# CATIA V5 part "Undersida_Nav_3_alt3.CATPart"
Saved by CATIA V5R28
Part number: Undersida_Nav_3
Bounding box of the stored display mesh (mm): x -107.108 to 82.814, y -82.361 to 109.652, z 0 to 70
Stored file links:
  H:\Maskiningenjör\Examensarbete\Klart\Klart & Skickas\Undersida_Nav_3_alt3.CATPart
  H:\Examensarbete\FullAssembly_KlartMedStativ\Assembly_Fullt+Stativ.CATProduct
  H:\Maskiningenjör\Examensarbete\Klart\Klart & Skickas\HJALPMEDEL.CATPart
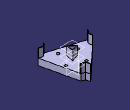
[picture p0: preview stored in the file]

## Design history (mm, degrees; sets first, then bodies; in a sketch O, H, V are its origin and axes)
Set1
  DatumPoint1 to DatumPoint4: linked copy from another document
Set2 "Sketches"
  Sketch1 "BasHubSketch" on xy-plane, origin (0, 0, 0), H (1, 0, 0), V (0, 1, 0)
    point P1 (14.1037, 15.4471)
    construction line L1 (14.1037, 15.4471) -> (-19.7235, 4.083)
    point P2 (-19.7235, 4.083)
    construction line L2 (-19.7235, 4.083) -> (7.0316, -19.5301)
    point P3 (7.0316, -19.5301)
    construction line L3 (7.0316, -19.5301) -> (14.1037, 15.4471)
    construction circle A1 centre (0.4706, 0) radius 10.3014
    point P4 (0.4706, 0)
    point P5 (2.4567, 169.7723)
    line L4 (2.4567, 169.7723) -> (-91.9658, -20.1866)
    point P6 (-91.9658, -20.1866)
    line L5 (-91.9658, -20.1866) -> (-147.5495, -83.1664)
    line L6 (-147.5495, -83.1664) -> (64.171, -69.9592)
    point P8 (64.171, -69.9592)
    line L7 (64.171, -69.9592) -> (146.5049, -86.6062)
    line L8 (146.5049, -86.6062) -> (29.2069, 90.1455)
    point P10 (29.2069, 90.1455)
    line L9 (29.2069, 90.1455) -> (2.4567, 169.7723)
    construction line L10 (29.2069, 90.1455) -> (64.171, -69.9592)
    construction line L11 (64.171, -69.9592) -> (-91.9658, -20.1866)
    construction line L12 (-91.9658, -20.1866) -> (29.2069, 90.1455)
    reference intersected line E1 through (0, 0) direction (0, 1) from yz-plane
    length L3 = 35.685
    length L1 = 35.685
    length L2 = 35.685
    length L9 = 84
    length L7 = 84
    length L5 = 84
    angle L9 L8 = 165
    angle L4 L5 = 165
    angle L6 L7 = 165
    distance P6 P8 = 163.878
    distance P6 P10 = 163.878
    distance P8 P10 = 163.878
    length L8 = 212.132 (reference)
    length L4 = 212.132 (reference)
    angle L10 V = 12.319
    length L6 = 212.132 (reference)
    distance P1 P10 = 76.21
    distance P2 P6 = 76.21
    angle L2 L5 = 90 (reference)
    distance P8 P3 = 76.2102
    distance P5 E1 = 2.4567
    tangency: A1 L3, A1 L1, A1 L2
    coincidence: P4 H
  Sketch2 "BasTriangelKoppling" on xy-plane, origin (0, 0, 0), H (1, 0, 0), V (0, 1, 0)
    line L1 (29.2069, 90.1455) -> (-91.9658, -20.1866)
    point P1 (29.2069, 90.1455)
    point P2 (-91.9658, -20.1866)
    line L2 (-91.9658, -20.1866) -> (64.171, -69.9592)
    point P3 (64.171, -69.9592)
    line L3 (64.171, -69.9592) -> (29.2069, 90.1455)
    reference projected point E1 (29.2069, 90.1455) from vertex [element of Sketch1 | element of Sketch1]
    reference projected point E2 (-91.9658, -20.1866) from vertex [element of Sketch1 | element of Sketch1]
    reference projected point E3 (64.171, -69.9592) from vertex [element of Sketch1 | element of Sketch1]
    coincidence: P1 E1, P2 E2, P3 E3
  Sketch3 "BenSketch" on Plane1, origin (0, 0, 30), H (1, 0, 0), V (0, 1, 0)
    point P1 (28.7362, 90.1456)
    line L1 (28.7362, 90.1456) -> (46.3521, 83.0267)
    point P2 (46.3521, 83.0267)
    line L2 (22.6855, 108.1564) -> (28.7362, 90.1456)
    point P3 (-92.4365, -20.1865)
    line L3 (-92.4365, -20.1865) -> (-95.0793, -1.3712)
    point P4 (-95.0793, -1.3712)
    line L4 (-105.009, -34.432) -> (-92.4365, -20.1865)
    point P5 (63.7003, -69.9591)
    line L5 (82.3234, -73.7245) -> (63.7003, -69.9591)
    line L6 (-107.1076, -33.7873) -> (-94.5183, -19.5229)
    point P7 (-94.5183, -19.5229)
    line L7 (-94.5183, -19.5229) -> (-96.8381, -3.007)
    line L8 (64.1665, -72.0938) -> (51.0232, -82.3608)
    point P9 (64.1665, -72.0938)
    line L9 (64.1665, -72.0938) -> (82.8145, -75.8642)
    line L10 (30.3518, 91.6167) -> (45.8149, 85.3678)
    point P12 (30.3518, 91.6167)
    line L11 (30.3518, 91.6167) -> (24.2931, 109.6515)
    line L12 (82.8145, -75.8642) -> (82.3234, -73.7245)
    point P15 (82.3234, -73.7245)
    line L13 (51.0232, -82.3608) -> (48.7272, -81.6555)
    point P16 (48.7272, -81.6555)
    line L14 (-107.1076, -33.7873) -> (-105.009, -34.432)
    point P18 (-95.0793, -1.3712)
    line L15 (-95.0793, -1.3712) -> (-96.8381, -3.007)
    line L16 (24.2931, 109.6515) -> (22.6855, 108.1564)
    line L17 (45.8149, 85.3678) -> (46.3521, 83.0267)
    point P20 (46.3521, 83.0267)
    line L18 (63.7003, -69.9591) -> (48.7272, -81.6555)
    construction line L19 (28.7362, 90.1456) -> (-92.4365, -20.1865)
    construction line L20 (-92.4365, -20.1865) -> (63.7003, -69.9591)
    construction line L21 (63.7003, -69.9591) -> (28.7362, 90.1456)
    construction line L22 (63.7003, -69.9591) -> (146.0342, -86.6061)
    construction line L23 (146.0342, -86.6061) -> (28.7362, 90.1456)
    construction line L24 (28.7362, 90.1456) -> (1.986, 169.7724)
    construction line L25 (1.986, 169.7724) -> (-92.4365, -20.1865)
    construction line L26 (-92.4365, -20.1865) -> (-148.0202, -83.1663)
    construction line L27 (-148.0202, -83.1663) -> (63.7003, -69.9591)
    construction line L28 (28.7362, 90.1456) -> (49.7278, 109.2592)
    construction line L29 (24.2931, 109.6515) -> (-96.8381, -3.007)
    construction line L30 (46.3521, 83.0267) -> (82.3234, -73.7245)
    construction line L31 (51.0232, -82.3608) -> (-105.009, -34.432)
    point P25 (46.2038, 10.1594)
    construction circle A1 centre (0, 0) radius 47.3075
    point P26 (0, 0)
    reference intersected line E1 through (0, 0) direction (0, 1) from yz-plane
    point P27 (-20.1941, 4.0829)
    point P28 (13.633, 15.4472)
    construction line L32 (13.633, 15.4472) -> (-20.1941, 4.0829)
    point P29 (6.5612, -19.5301)
    construction line L33 (6.5612, -19.5301) -> (13.633, 15.4472)
    construction line L34 (-20.1941, 4.0829) -> (6.5612, -19.5301)
    angle L2 L1 = 130.574
    angle L3 L4 = 130.574
    distance L6 L4 = 2
    distance L9 L5 = 2
    distance L2 L11 = 2
    angle L18 L5 = 130.574
    distance P15 P5 = 19
    distance P16 P5 = 19
    length L2 = 19
    length L1 = 19
    length L4 = 19
    length L3 = 19
    length L23 = 212.132
    length L22 = 84
    length L27 = 212.132
    length L26 = 84
    length L25 = 212.132
    length L24 = 84
    length L20 = 163.878
    length L19 = 163.878
    length L21 = 163.878
    angle E1 L21 = 12.319
    angle L24 L23 = 165 (reference)
    distance P1 P28 = 76.21
    distance P29 P5 = 76.21
    distance P27 P3 = 76.21
    angle L32 L3 = 79.4257
    angle L18 L34 = 79.4257
    angle L1 L33 = 79.4257
    parallelism: L7 L3, L10 L1, L18 L8, L9 L5
    coincidence: P4 P18, P20 L1, P2 P20, L5 L22, L2 L24, L28 L19, P12 L28, P9 L21, P7 L20, L15 L29, L16 L29, L17 L30, L12 L30, L13 L31, L14 L31, L4 L26, P25 L21, P26 O
    tangency: A1 L20, A1 L21, A1 L19
  Sketch4 "BaseSketch" on xy-plane, origin (0, 0, 0), H (1, 0, 0), V (0, 1, 0)
    line L1 (45.8149, 85.3678) -> (82.8145, -75.8642)
    point P1 (45.8149, 85.3678)
    point P2 (82.8145, -75.8642)
    line L2 (24.2931, 109.6515) -> (-96.8381, -3.007)
    point P3 (24.2931, 109.6515)
    point P4 (-96.8381, -3.007)
    line L3 (-107.1076, -33.7873) -> (51.0232, -82.3608)
    point P5 (-107.1076, -33.7873)
    point P6 (51.0232, -82.3608)
    line L4 (51.0232, -82.3608) -> (64.1665, -72.0938)
    point P7 (64.1665, -72.0938)
    line L5 (64.1665, -72.0938) -> (82.8145, -75.8642)
    line L6 (-107.1076, -33.7873) -> (-94.5183, -19.5229)
    point P8 (-94.5183, -19.5229)
    line L7 (-94.5183, -19.5229) -> (-96.8381, -3.007)
    line L8 (24.2931, 109.6515) -> (30.3518, 91.6167)
    point P9 (30.3518, 91.6167)
    line L9 (30.3518, 91.6167) -> (45.8149, 85.3678)
    reference projected point E1 (45.8149, 85.3678) from vertex [element of Sketch3 | element of Sketch3]
    reference projected point E2 (24.2931, 109.6515) from vertex [element of Sketch3 | element of Sketch3]
    reference projected point E3 (30.3518, 91.6167) from vertex [element of Sketch3 | element of Sketch3]
    reference projected point E4 (82.8145, -75.8642) from vertex [element of Sketch3 | element of Sketch3]
    reference projected point E5 (51.0232, -82.3608) from vertex [element of Sketch3 | element of Sketch3]
    reference projected point E6 (64.1665, -72.0938) from vertex [element of Sketch3 | element of Sketch3]
    reference projected point E7 (-96.8381, -3.007) from vertex [element of Sketch3 | element of Sketch3]
    reference projected point E8 (-107.1076, -33.7873) from vertex [element of Sketch3 | element of Sketch3]
    reference projected point E9 (-94.5183, -19.5229) from vertex [element of Sketch3 | element of Sketch3]
    coincidence: P1 E1, P3 E2, P9 E3, P2 E4, P6 E5, P7 E6, P4 E7, P5 E8, P8 E9
  Sketch5 "UndersideHole" on xy-plane, origin (0, 0, 0), H (1, 0, 0), V (0, 1, 0)
    circle A1 centre (0, 0) radius 26
    radius A1 = 26
    concentricity: A1 O
  Sketch6 "MiddleTriangle" on Plane1, origin (0, 0, 30), H (1, 0, 0), V (0, 1, 0)
    point P1 (-20.1941, 4.0829)
    point P2 (13.633, 15.4472)
    line L1 (13.633, 15.4472) -> (-20.1941, 4.0829)
    point P3 (6.5612, -19.5301)
    line L2 (6.5612, -19.5301) -> (13.633, 15.4472)
    construction circle A1 centre (0, 0) radius 10.3014
    line L3 (-20.1941, 4.0829) -> (6.5612, -19.5301)
    reference projected line E1 (29.15, 89.9784) -> (46.7659, 82.8595) from Sketch3.L1
    reference projected line E2 (64.0282, -69.7029) -> (49.0551, -81.3993) from Sketch3.L18
    reference projected point E3 (-92.4365, -20.1865) from vertex [element of Sketch3 | element of Sketch3]
    reference projected point E4 (-92.4365, -20.1865) from vertex [element of Sketch3 | element of Sketch3]
    reference projected point E5 (28.7362, 90.1456) from vertex [element of Sketch3 | element of Sketch3]
    reference projected point E6 (63.7003, -69.9591) from vertex [element of Sketch3 | element of Sketch3]
    reference projected line E7 (-92.4323, -20.2164) -> (-95.0751, -1.4011) from Sketch3.L3
    length L2 = 35.685
    length L1 = 35.685
    length L3 = 35.685
    angle E1 L2 = 79.4257 (reference)
    angle L3 E2 = 79.4257 (reference)
    distance P1 E3 = 76.21 (reference)
    distance E4 P1 = 76.21
    distance P2 E5 = 76.21
    distance P3 E6 = 76.21
    angle E7 L1 = 79.4257 (reference)
    tangency: A1 L2, A1 L3, A1 L1
  Sketch7 "InnerTriangle" on Plane3, origin (0, 0, 70), H (1, 0, 0), V (0, 1, 0)
    construction line L1 (13.6331, 15.4471) -> (-20.1941, 4.083)
    point P3 (6.5611, -19.5301)
    construction line L2 (6.5611, -19.5301) -> (13.6331, 15.4471)
    construction line L3 (-20.1941, 4.083) -> (6.5611, -19.5301)
    point P4 (0, 0)
    construction circle A1 centre (0, 0) radius 10.3014
    line L4 (9.2639, 10.4966) -> (-13.7223, 2.7745)
    line L5 (-13.7223, 2.7745) -> (4.4584, -13.2711)
    line L6 (4.4584, -13.2711) -> (9.2639, 10.4966)
    construction circle A2 centre (0, 0) radius 7
    reference projected line E1 (-19.9341, 3.8534) -> (6.8212, -19.7596) from Sketch6.L3
    reference projected line E2 (64.0282, -69.7029) -> (49.0551, -81.3993) from Sketch3.L18
    reference projected line E3 (6.5883, -19.3957) -> (13.6601, 15.5816) from Sketch6.L2
    reference projected line E4 (29.15, 89.9784) -> (46.7659, 82.8595) from Sketch3.L1
    reference projected line E5 (-92.4323, -20.2164) -> (-95.0751, -1.4011) from Sketch3.L3
    reference projected point E6 (63.7003, -69.9591) from vertex [element of Sketch3 | element of Sketch3]
    length L1 = 35.685
    length L2 = 35.685
    length L3 = 35.685
    angle E1 E2 = 79.4257 (reference)
    angle E3 E4 = 79.4257 (reference)
    angle E5 L1 = 79.426
    distance P3 E6 = 76.2101 (reference)
    radius A2 = 7
    tangency: A1 L1, A1 L2, A1 L3, A2 L5, A2 L4, A2 L6
    coincidence: P4 O
    parallelism: L5 L3, L4 L1, L6 L2
Set3 "ExtraSketches"
  Sketch8 on Plane2, origin (0, 0, 70), H (1, 0, 0), V (0, 1, 0)
    point P1 (29.2069, 90.1455)
    construction line L1 (29.2069, 90.1455) -> (45.8796, 83.3617)
    construction line L2 (45.8796, 83.3617) -> (43.2556, 102.9374)
    point P3 (43.2556, 102.9374)
    construction line L3 (43.2556, 102.9374) -> (22.8378, 109.1043)
    construction line L4 (22.8378, 109.1043) -> (29.2069, 90.1455)
    point P5 (-91.9658, -20.1866)
    construction line L5 (-91.9658, -20.1866) -> (-94.491, -2.3646)
    construction line L6 (-94.491, -2.3646) -> (-110.0683, -14.416)
    point P7 (-110.0683, -14.416)
    construction line L7 (-110.0683, -14.416) -> (-105.2, -35.1818)
    construction line L8 (-105.2, -35.1818) -> (-91.9658, -20.1866)
    point P9 (64.171, -69.9592)
    construction line L9 (64.171, -69.9592) -> (49.9993, -81.057)
    construction line L10 (49.9993, -81.057) -> (68.2247, -88.5217)
    point P11 (68.2247, -88.5217)
    construction line L11 (68.2247, -88.5217) -> (83.7743, -73.9227)
    construction line L12 (83.7743, -73.9227) -> (64.171, -69.9592)
    reference projected point E1 (29.2069, 90.1455) from vertex [element of Sketch2 | element of Sketch2]
    construction line L13 (4.7862, 67.9096) -> (62.2514, 120.2338)
    reference projected line E2 (27.0028, 88.1386) -> (-89.0375, -17.5203) from Sketch2.L1
    construction line L14 (-154.2129, -0.3438) -> (-41.3139, -36.3332)
    reference projected line E3 (-89.7482, -20.8935) -> (59.6074, -68.5044) from Sketch2.L2
    reference projected point E4 (-91.9658, -20.1866) from vertex [element of Sketch2 | element of Sketch2]
    construction line L15 (59.6572, -49.2902) -> (72.3238, -107.2918)
    reference projected line E5 (63.5408, -67.0736) -> (30.083, 86.1336) from Sketch2.L3
    reference projected point E6 (64.171, -69.9592) from vertex [element of Sketch2 | element of Sketch2]
    reference projected line E7 (-92.1398, -20.3838) -> (-149.5902, -85.4786) from Sketch1.L5
    reference projected line E8 (29.1039, 90.4521) -> (1.4553, 172.753) from Sketch1.L9
    reference projected line E9 (63.7621, -69.8765) -> (148.8611, -87.0826) from Sketch1.L7
    point P19 (64.811, -72.8901)
    line L16 (64.811, -72.8901) -> (78.2238, -75.602)
    line L17 (78.2238, -75.602) -> (67.5846, -85.5908)
    point P21 (67.5846, -85.5908)
    line L18 (67.5846, -85.5908) -> (55.1146, -80.4834)
    line L19 (55.1146, -80.4834) -> (64.811, -72.8901)
    line L20 (-96.5519, -7.0815) -> (-107.21, -15.3271)
    point P24 (-107.21, -15.3271)
    line L21 (-107.21, -15.3271) -> (-103.8791, -29.5353)
    line L22 (-103.8791, -29.5353) -> (-94.8241, -19.2754)
    point P26 (-94.8241, -19.2754)
    line L23 (-94.8241, -19.2754) -> (-96.5519, -7.0815)
    point P27 (41.0374, 100.9177)
    line L24 (41.0374, 100.9177) -> (42.8328, 87.5237)
    line L25 (42.8328, 87.5237) -> (31.4251, 92.1653)
    point P29 (31.4251, 92.1653)
    line L26 (31.4251, 92.1653) -> (27.0673, 105.1371)
    line L27 (27.0673, 105.1371) -> (41.0374, 100.9177)
    length L1 = 18
    length L4 = 20
    angle L4 L1 = 130.71
    length L8 = 20
    length L5 = 18
    angle L5 L8 = 130.505
    length L12 = 20
    length L9 = 18
    angle L9 L12 = 130.505
    distance P7 P5 = 19
    distance P1 P3 = 19
    distance P11 P9 = 19
    distance P19 P21 = 13
    distance P19 P9 = 3
    distance P24 P26 = 13
    distance P26 P5 = 3
    distance P29 P1 = 3
    distance P29 P27 = 13
    coincidence: P1 E1, L13 E2, P3 L13, L14 E3, P7 L14, P5 E4, L15 E5, P9 E6, P11 L15, L8 E7, L4 E8, L12 E9, P19 L15, P21 L15, P24 L14, P26 L14, P27 L13, P29 L13
    parallelism: L18 L10, L19 L9, L17 L11, L16 L12, L21 L7, L22 L8, L20 L6, L23 L5, L24 L2, L25 L1, L26 L4, L27 L3
Set4 "Fills"
  Fill1 "UnderFill_Bas": Boundary Sketch4, InnerBoundaries {fillinnerboundary Boundaries Sketch5}
  Fill2 "UpperFill_Bas": Boundary (edge of Extrude2; edge of Extrude2; edge of Extrude2; edge of Extrude2; edge of Extrude2; edge of Extrude2; edge of Extrude2; edge of Extrude2; edge of Extrude2)
  Fill3 "CornerTopFill1": Boundary Sketch3
  Fill4: Boundary (edge of Extrude1; edge of Extrude1; edge of Extrude1; edge of Extrude1; edge of Extrude1; edge of Extrude1)
  Fill5: Boundary (edge of Extrude1; edge of Extrude1; edge of Extrude1; edge of Extrude1; edge of Extrude1; edge of Extrude1)
  Fill6: Boundary (edge of Extrude1; edge of Extrude1; edge of Extrude1; edge of Extrude1; edge of Extrude1; edge of Extrude1)
  Fill7 "TriangleFill": Boundary (edge of Extrude4; edge of Extrude4; edge [face of CloseSurface1 | face of CloseSurface1])
Set5 "Planes"
  Plane1: type Offset, RefPlane xy-plane, Offset 30
  Plane2 "CornerPillarsPlane": type Offset, RefPlane Plane1, Offset 40
  Plane3 "TriangleLengthPlane": type Offset, RefPlane Plane1, Offset 40
Set6 "Extrudes"
  Extrude1 "CornerPillar_Extrudes": Element1 Sketch3, Lim1 20, Lim2 0, FirstUpto Plane2
  Extrude2 "Bas_Extrude": Element1 Sketch4, Lim1 20, Lim2 0, FirstUpto Plane1
  Extrude3 "MiddleBaseHole": Element1 Sketch5, Lim1 18, Lim2 0
  Extrude4 "TriangleExtrude": Element1 Sketch6, Lim1 29, Lim2 0, FirstUpto Plane3
Set7 "Joins"
  Join1: Elements (Fill1; Extrude2; Extrude3; Trim1; Fill4; Fill5; Fill6)
Set8 "Trims"
  Trim1: Trimmed (Extrude1; Fill2; Extrude4)
Body1 (main body)
  CloseSurface1: CloseElement Join1
  Pocket1: profile Sketch7, direction (0, 0, -1), length 30
  Sketch9, origin (19.0383, -48.2652, 0), H (1, 0, 0), V (0, -1, 0), geometry linked from another document
  Hole1: placed by Sketch9, at (18.7916, -47.5306, 0) direction (0, 0, 1), diameter 12, through (limit type 3)
  Sketch10, origin (47.6678, 17.798, 0), H (1, 0, 0), V (0, -1, 0), geometry linked from another document
  Hole2: placed by Sketch10, at (47.421, 18.5326, 0) direction (0, 0, 1), diameter 12, through (limit type 3)
  Sketch11, origin (-47.0249, -19.6358, 0), H (1, 0, 0), V (0, -1, 0), geometry linked from another document
  Hole3: placed by Sketch11, at (-47.2717, -18.9012, 0) direction (0, 0, 1), diameter 12, through (limit type 3)
  Sketch12, origin (-18.3955, 46.4275, 0), H (1, 0, 0), V (0, -1, 0), geometry linked from another document
  Hole4: placed by Sketch12, at (-18.6423, 47.1621, 0) direction (0, 0, 1), diameter 12, through (limit type 3)
  Sketch13 "Positioning sketch - Assembly Hole.5" on face of CloseSurface1, origin (19.0383, -48.2652, 0), H (1, 0, 0), V (0, -1, 0)
    point P1 (-0.2468, -0.7346)
    reference projected point E1 (-0.2468, -0.7346) from vertex of DatumPoint1
    coincidence: E1 P1
  Sketch14 "Positioning sketch - Assembly Hole.6" on face of CloseSurface1, origin (47.6678, 17.798, 0), H (1, 0, 0), V (0, -1, 0)
    point P1 (-0.2468, -0.7346)
    reference projected point E1 (-0.2468, -0.7346) from vertex of DatumPoint2
    coincidence: E1 P1
  Sketch15 "Positioning sketch - Assembly Hole.7" on face of CloseSurface1, origin (-47.0249, -19.6358, 0), H (1, 0, 0), V (0, -1, 0)
    point P1 (-0.2468, -0.7346)
    reference projected point E1 (-0.2468, -0.7346) from vertex of DatumPoint3
    coincidence: E1 P1
  Sketch16 "Positioning sketch - Assembly Hole.8" on face of CloseSurface1, origin (-18.3955, 46.4275, 0), H (1, 0, 0), V (0, -1, 0)
    point P1 (-0.2468, -0.7346)
    reference projected point E1 (-0.2468, -0.7346) from vertex of DatumPoint4
    coincidence: E1 P1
